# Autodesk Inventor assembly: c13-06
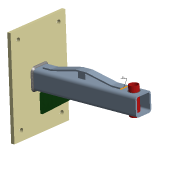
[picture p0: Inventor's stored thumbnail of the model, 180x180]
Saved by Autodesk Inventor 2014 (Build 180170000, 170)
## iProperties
Created: 2011-01
Part Number: c13-06
Document SubType Name: Weldment
Designer: Thom Tremblay
Weld Material: Welded Steel Mild
_SolveAssemblyDoc: Frame Generator Solve Assembly
_Version: 15.0.0
Author: Thom Tremblay
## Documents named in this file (5)
- C:\Inventor 2014 Essentials\Assemblies\Chapter 13\c13-06.iam
- C:\Inventor 2014 Essentials\Parts\Chapter 13\c13-01.ipt
- C:\Inventor 2014 Essentials\Parts\Chapter 13\c13-02.ipt
- C:\Inventor 2014 Essentials\Assemblies\Chapter 13\Frame\Frame c13-01.iam
- C:\Inventor 2014 Essentials\Parts\Chapter 13\c13-03.ipt
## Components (4 placed, 4 different names)
1. c13-01:1 — Mate:2
2. c13-02:1 — Flush:1
3. Frame c13-01:1 [sub-assembly] — Mate:3
4. c13-03:1 — Mate:1, Mate:2, Mate:3
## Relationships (4: Mate 3, Flush 1)
- Flush:1: c13-02:1
- Mate:1: c13-03:1
- Mate:2: c13-01:1 ↔ c13-03:1
- Mate:3: Frame c13-01:1 ↔ c13-03:1
